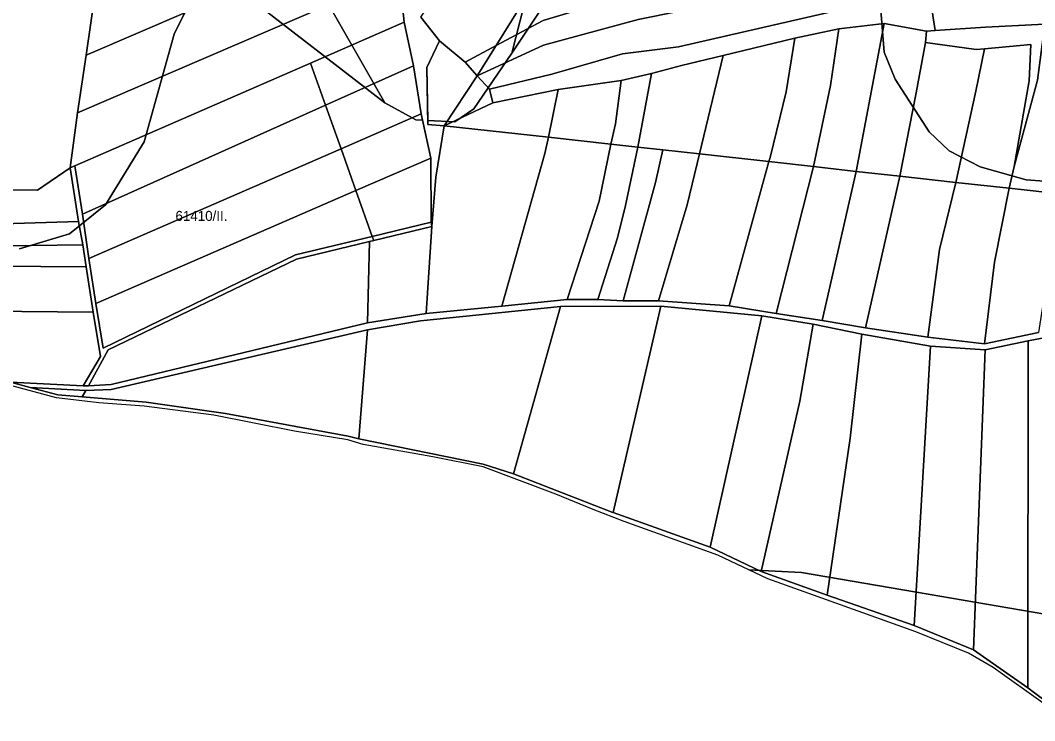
# Model space of a CAD drawing. Extents: x -521261 to -517465, y -1182764 to -1179456.
# Drawn here: x -520761 to -520253, y -1181838 to -1181488 of the extents above; entities that cross this region are included whole.
import ezdxf

# ---------------------------------------------------------------- set-up
doc = ezdxf.new("R2010")
doc.units = 0
for name, color, linetype in [('95560013', 7, 'Continuous'), ('95610013', 7, 'Continuous'), ('95620013', 7, 'Continuous'), ('95640013', 7, 'Continuous'), ('95660013', 7, 'Continuous')]:
    doc.layers.add(name, color=color, linetype=linetype)

msp = doc.modelspace()

# ---------------------------------------------------------------- linework, layer by layer
at = {"layer": '95560013'}
for points in [[(-520576.08, -1181410.39), (-520574.24, -1181438.77), (-520728.04, -1181505.07), (-520723.52, -1181473.69)], [(-520574.24, -1181438.77), (-520571.45, -1181464.53), (-520732.41, -1181533.87), (-520728.04, -1181505.07)], [(-520571.45, -1181464.53), (-520568.81, -1181488.5), (-520615.8, -1181509), (-520733.75, -1181560.43), (-520736.16, -1181561.46), (-520732.41, -1181533.87)], [(-520615.8, -1181509), (-520608.28, -1181530.11), (-520729.99, -1181584.7), (-520733.75, -1181560.43)], [(-520608.28, -1181530.11), (-520600.48, -1181552.02), (-520726.79, -1181606.86), (-520729.99, -1181584.7)], [(-520548.78, -1181540.39), (-520496.59, -1181546.1), (-520498.54, -1181554.32), (-520520.06, -1181630.73), (-520557.91, -1181634.34), (-520554.96, -1181590.89), (-520552.96, -1181566.19)], [(-520496.59, -1181546.1), (-520465.4, -1181549.66), (-520471.23, -1181578.21), (-520487.32, -1181627.42), (-520520.06, -1181630.73), (-520498.54, -1181554.32)], [(-520600.48, -1181552.02), (-520593.06, -1181572.76), (-520723.2, -1181629.37), (-520726.79, -1181606.86)], [(-520465.4, -1181549.66), (-520451.84, -1181551.12), (-520458.04, -1181580.38), (-520462.09, -1181596.51), (-520471.99, -1181627.44), (-520487.32, -1181627.42), (-520471.23, -1181578.21)], [(-520451.84, -1181551.12), (-520439.46, -1181552.51), (-520443.1, -1181568.75), (-520459.22, -1181628.09), (-520471.99, -1181627.44), (-520462.09, -1181596.51), (-520458.04, -1181580.38)], [(-520439.46, -1181552.51), (-520421.04, -1181554.54), (-520427.16, -1181580), (-520441.6, -1181628.06), (-520459.22, -1181628.09), (-520443.1, -1181568.75)], [(-520421.04, -1181554.54), (-520386.32, -1181558.37), (-520406.18, -1181630.57), (-520441.6, -1181628.06), (-520427.16, -1181580)], [(-520386.32, -1181558.37), (-520363.9, -1181560.85), (-520382.71, -1181634.48), (-520406.18, -1181630.57)], [(-520886.32, -1181568.63), (-520832.67, -1181568.56), (-520804.67, -1181572.45), (-520752.43, -1181572.59), (-520736.16, -1181561.46), (-520731.92, -1181588.39), (-520937.51, -1181594.75), (-520938.5, -1181584.87), (-520905.87, -1181574.73)], [(-520736.16, -1181561.46), (-520733.75, -1181560.43), (-520729.99, -1181584.7), (-520726.79, -1181606.86), (-520723.2, -1181629.37), (-520719.64, -1181651.68), (-520623.26, -1181604.99), (-520584.89, -1181595.78), (-520584.13, -1181597.91), (-520586.26, -1181598.42), (-520622.78, -1181607.14), (-520717.05, -1181652.63), (-520726.99, -1181670.56), (-520729.64, -1181670.6), (-520720.88, -1181655.89), (-520724.61, -1181633.78), (-520728.15, -1181611.04), (-520729.78, -1181600.02), (-520731.92, -1181588.39)], [(-520363.9, -1181560.85), (-520342.59, -1181563.26), (-520359.55, -1181637.84), (-520382.71, -1181634.48)], [(-520342.59, -1181563.26), (-520320.65, -1181565.69), (-520337.87, -1181641.62), (-520359.55, -1181637.84)], [(-520320.65, -1181565.69), (-520292.74, -1181568.76), (-520300.88, -1181602.38), (-520306.66, -1181646.26), (-520337.87, -1181641.62)], [(-520292.74, -1181568.76), (-520266.02, -1181571.63), (-520273.4, -1181608.7), (-520278.33, -1181649.59), (-520306.66, -1181646.26), (-520300.88, -1181602.38)], [(-520593.06, -1181572.76), (-520584.89, -1181595.78), (-520623.26, -1181604.99), (-520719.64, -1181651.68), (-520723.2, -1181629.37)], [(-520266.02, -1181571.63), (-520237.7, -1181574.77), (-520245.8, -1181608.4), (-520251.25, -1181643.84), (-520278.33, -1181649.59), (-520273.4, -1181608.7)], [(-520937.51, -1181594.75), (-520731.92, -1181588.39), (-520729.78, -1181600.02), (-520936.72, -1181602.63)], [(-520584.13, -1181597.91), (-520554.96, -1181590.89), (-520557.91, -1181634.34), (-520587.19, -1181639.08), (-520586.26, -1181598.42)], [(-520622.78, -1181607.14), (-520586.26, -1181598.42), (-520587.19, -1181639.08), (-520715.64, -1181669.99), (-520726.99, -1181670.56), (-520717.05, -1181652.63)], [(-520936.72, -1181602.63), (-520729.78, -1181600.02), (-520728.15, -1181611.04), (-520931.87, -1181609.45), (-520936.19, -1181607.92)], [(-520931.87, -1181609.45), (-520728.15, -1181611.04), (-520724.61, -1181633.78), (-520867.79, -1181632.34)], [(-520867.79, -1181632.34), (-520724.61, -1181633.78), (-520720.88, -1181655.89), (-520729.64, -1181670.6), (-520766.06, -1181668.83), (-520786.46, -1181661.6), (-520801.3, -1181657.2), (-520847.78, -1181646.82), (-520860.23, -1181635.71), (-520861.47, -1181634.59)], [(-520560.75, -1181638.05), (-520490.54, -1181630.82), (-520514.2, -1181714.71), (-520529.3, -1181709.77), (-520591.66, -1181697.2), (-520587.21, -1181642.65)], [(-520490.54, -1181630.82), (-520440.41, -1181630.77), (-520464.25, -1181734.09), (-520464.47, -1181734.01), (-520514.2, -1181714.71)], [(-520440.41, -1181630.77), (-520389.82, -1181635.53), (-520415.77, -1181751.31), (-520464.25, -1181734.09)], [(-520389.82, -1181635.53), (-520364.08, -1181639.81), (-520370.75, -1181678.21), (-520390.13, -1181763.62), (-520415.77, -1181751.31)], [(-520364.08, -1181639.81), (-520339.69, -1181644.68), (-520345.66, -1181696.87), (-520357.16, -1181775.41), (-520390.13, -1181763.62), (-520370.75, -1181678.21)], [(-520715.51, -1181672.43), (-520587.21, -1181642.65), (-520591.66, -1181697.2), (-520597, -1181695.88), (-520658.38, -1181684.44), (-520698.04, -1181678.72), (-520730.06, -1181676.1), (-520728.23, -1181673.03)], [(-520339.69, -1181644.68), (-520305.4, -1181650.72), (-520313.52, -1181790.53), (-520357.16, -1181775.41), (-520345.66, -1181696.87)], [(-520256.52, -1181648.14), (-520237.89, -1181644.57), (-520230.95, -1181838.28), (-520247.99, -1181828.33), (-520256.67, -1181821.86)], [(-520277.95, -1181652.57), (-520256.52, -1181648.14), (-520256.67, -1181821.86), (-520272.09, -1181811.02), (-520283.89, -1181802.78)], [(-520305.4, -1181650.72), (-520277.95, -1181652.57), (-520283.89, -1181802.78), (-520313.52, -1181790.53)], [(-520756.08, -1181671.43), (-520728.23, -1181673.03), (-520730.06, -1181676.1), (-520742.28, -1181675.11)]]:
    msp.add_lwpolyline(points, close=True, dxfattribs=at)
msp.add_lwpolyline([(-520237.89, -1181644.57), (-520256.52, -1181648.14), (-520277.95, -1181652.57), (-520305.4, -1181650.72), (-520339.69, -1181644.68), (-520364.08, -1181639.81), (-520389.82, -1181635.53), (-520440.41, -1181630.77), (-520490.54, -1181630.82), (-520560.75, -1181638.05), (-520587.21, -1181642.65), (-520715.51, -1181672.43), (-520728.23, -1181673.03), (-520756.08, -1181671.43), (-520766.06, -1181668.83), (-520729.64, -1181670.6), (-520726.99, -1181670.56), (-520715.64, -1181669.99), (-520587.19, -1181639.08), (-520557.91, -1181634.34), (-520520.06, -1181630.73), (-520487.32, -1181627.42), (-520471.99, -1181627.44), (-520459.22, -1181628.09), (-520441.6, -1181628.06), (-520406.18, -1181630.57), (-520382.71, -1181634.48), (-520359.55, -1181637.84), (-520337.87, -1181641.62), (-520306.66, -1181646.26), (-520278.33, -1181649.59), (-520251.25, -1181643.84)], dxfattribs=at)
at = {"layer": '95610013'}
for points in [[(-520454.87, -1181427.08), (-520391.32, -1181413.46), (-520408.16, -1181427.45), (-520448.41, -1181473.09), (-520453.82, -1181473.89), (-520499.28, -1181487.67), (-520522.86, -1181500.26), (-520482.21, -1181434.76)], [(-520364.32, -1181456), (-520313.09, -1181448.84), (-520310.06, -1181461.77), (-520349.03, -1181466.33), (-520451.71, -1181487.19), (-520499.12, -1181500), (-520532.26, -1181515.4), (-520522.86, -1181500.26), (-520499.28, -1181487.67), (-520453.82, -1181473.89), (-520448.41, -1181473.09), (-520445.12, -1181472.67)], [(-520310.06, -1181461.77), (-520307.52, -1181472.34), (-520307.98, -1181477.97), (-520351.52, -1181482.6), (-520431.47, -1181500.94), (-520459.61, -1181504.33), (-520494.99, -1181514.51), (-520526.22, -1181522.02), (-520532.26, -1181515.4), (-520499.12, -1181500), (-520451.71, -1181487.19), (-520349.03, -1181466.33)], [(-520305.37, -1181477.77), (-520303.01, -1181492.71), (-520307.36, -1181492.97), (-520328.5, -1181489.14), (-520351.25, -1181491.92), (-520373.3, -1181496.48), (-520409.22, -1181505.26), (-520429.99, -1181510.25), (-520445.11, -1181514.18), (-520460.28, -1181517.71), (-520491.73, -1181522.23), (-520524.43, -1181529), (-520526.22, -1181522.02), (-520494.99, -1181514.51), (-520459.61, -1181504.33), (-520431.47, -1181500.94), (-520351.52, -1181482.6), (-520307.98, -1181477.97)], [(-520373.3, -1181496.48), (-520351.25, -1181491.92), (-520355.45, -1181520.3), (-520363.9, -1181560.85), (-520386.32, -1181558.37), (-520385.73, -1181556.24), (-520377.61, -1181523.41)], [(-520351.25, -1181491.92), (-520328.5, -1181489.14), (-520342.59, -1181563.26), (-520363.9, -1181560.85), (-520355.45, -1181520.3)], [(-520328.5, -1181489.14), (-520307.36, -1181492.97), (-520307.94, -1181498.71), (-520312.51, -1181523.85), (-520320.65, -1181565.69), (-520342.59, -1181563.26)], [(-520248.06, -1181489.62), (-520251.84, -1181517.59), (-520263.43, -1181560.87), (-520255.94, -1181517.97), (-520255.16, -1181499.72), (-520278.35, -1181501.97), (-520282.48, -1181502.26), (-520307.94, -1181498.71), (-520307.36, -1181492.97), (-520303.01, -1181492.71), (-520277.86, -1181490.96)], [(-520222.29, -1181489.55), (-520229.64, -1181542.18), (-520237.7, -1181574.77), (-520266.02, -1181571.63), (-520263.43, -1181560.87), (-520251.84, -1181517.59), (-520248.06, -1181489.62)], [(-520409.22, -1181505.26), (-520373.3, -1181496.48), (-520377.61, -1181523.41), (-520385.73, -1181556.24), (-520386.32, -1181558.37), (-520421.04, -1181554.54)], [(-520282.48, -1181502.26), (-520278.35, -1181501.97), (-520282.61, -1181523.15), (-520292.74, -1181568.76), (-520320.65, -1181565.69), (-520312.51, -1181523.85), (-520307.94, -1181498.71)], [(-520278.35, -1181501.97), (-520255.16, -1181499.72), (-520255.94, -1181517.97), (-520263.43, -1181560.87), (-520266.02, -1181571.63), (-520292.74, -1181568.76), (-520282.61, -1181523.15)], [(-520429.99, -1181510.25), (-520409.22, -1181505.26), (-520421.04, -1181554.54), (-520439.46, -1181552.51), (-520451.84, -1181551.12), (-520445.11, -1181514.18)], [(-520532.26, -1181515.4), (-520526.22, -1181522.02), (-520524.43, -1181529), (-520548.78, -1181540.39)], [(-520491.73, -1181522.23), (-520460.28, -1181517.71), (-520463.12, -1181539.42), (-520465.4, -1181549.66), (-520496.59, -1181546.1)], [(-520460.28, -1181517.71), (-520445.11, -1181514.18), (-520451.84, -1181551.12), (-520465.4, -1181549.66), (-520463.12, -1181539.42)], [(-520524.43, -1181529), (-520491.73, -1181522.23), (-520496.59, -1181546.1), (-520548.78, -1181540.39)]]:
    msp.add_lwpolyline(points, close=True, dxfattribs=at)
at = {"layer": '95620013'}
msp.add_lwpolyline([(-520220.56, -1181464.03), (-520188.68, -1181456.43), (-520183.26, -1181487.11), (-520201.97, -1181488.21), (-520211.67, -1181488.9), (-520222.29, -1181489.55), (-520248.06, -1181489.62), (-520277.86, -1181490.96), (-520303.01, -1181492.71), (-520305.37, -1181477.77), (-520276.65, -1181475.26), (-520249.84, -1181470.67)], close=True, dxfattribs=at)
for points in [[(-520560.55, -1181486.11), (-520551.17, -1181497.81), (-520557.58, -1181511.29), (-520557.03, -1181539.8), (-520548.78, -1181540.39), (-520552.96, -1181566.19), (-520554.96, -1181590.89), (-520555.33, -1181588.67), (-520555.55, -1181556.57), (-520560.33, -1181534.47), (-520564.22, -1181510.35), (-520568.81, -1181488.5), (-520571.45, -1181464.53)], [(-520723.52, -1181473.69), (-520728.04, -1181505.07), (-520732.41, -1181533.87), (-520736.16, -1181561.46), (-520752.43, -1181572.59), (-520804.67, -1181572.45)]]:
    msp.add_lwpolyline(points, dxfattribs=at)
at = {"layer": '95640013'}
for points in [[(-520497.08, -1181439.12), (-520482.21, -1181434.76), (-520522.86, -1181500.26), (-520538.34, -1181508.53), (-520551.17, -1181497.81), (-520560.55, -1181486.11), (-520545.05, -1181462.49), (-520518.89, -1181450.27)], [(-520568.81, -1181488.5), (-520564.22, -1181510.35), (-520608.28, -1181530.11), (-520615.8, -1181509)], [(-520551.17, -1181497.81), (-520538.34, -1181508.53), (-520532.26, -1181515.4), (-520548.78, -1181540.39), (-520557.03, -1181539.8), (-520557.58, -1181511.29)], [(-520538.34, -1181508.53), (-520522.86, -1181500.26), (-520532.26, -1181515.4)], [(-520608.28, -1181530.11), (-520564.22, -1181510.35), (-520560.33, -1181534.47), (-520600.48, -1181552.02)], [(-520600.48, -1181552.02), (-520560.33, -1181534.47), (-520555.55, -1181556.57), (-520593.06, -1181572.76)], [(-520593.06, -1181572.76), (-520555.55, -1181556.57), (-520555.33, -1181588.67), (-520584.89, -1181595.78)], [(-520554.96, -1181590.89), (-520584.13, -1181597.91), (-520584.89, -1181595.78), (-520555.33, -1181588.67)]]:
    msp.add_lwpolyline(points, close=True, dxfattribs=at)
for points in [[(-520247.74, -1181830.3), (-520273.94, -1181811.64), (-520286.37, -1181804.39), (-520312.77, -1181793.79), (-520352.8, -1181779.41), (-520386.86, -1181767.21), (-520411.78, -1181755.41), (-520458.77, -1181738.57), (-520474.31, -1181732.61), (-520492.99, -1181724.81), (-520529.33, -1181711.19), (-520554.52, -1181706.12), (-520589.48, -1181699.97), (-520597.15, -1181697.6), (-520623.84, -1181693.35), (-520664.1, -1181685.3), (-520698.99, -1181680.78), (-520721.77, -1181679.06), (-520742.99, -1181676.7), (-520767.86, -1181669.98)], [(-520766.06, -1181668.83), (-520756.08, -1181671.43), (-520742.28, -1181675.11), (-520730.06, -1181676.1), (-520698.04, -1181678.72), (-520658.38, -1181684.44), (-520597, -1181695.88), (-520591.66, -1181697.2), (-520529.3, -1181709.77), (-520514.2, -1181714.71), (-520464.47, -1181734.01), (-520464.25, -1181734.09), (-520415.77, -1181751.31), (-520390.13, -1181763.62), (-520357.16, -1181775.41), (-520313.52, -1181790.53), (-520283.89, -1181802.78), (-520272.09, -1181811.02), (-520256.67, -1181821.86), (-520247.99, -1181828.33)]]:
    msp.add_lwpolyline(points, dxfattribs=at)
at = {"layer": '95660013'}
for points in [[(-520333.5, -1181440.5), (-520328.5, -1181503.5), (-520323, -1181517), (-520306, -1181543.5), (-520296, -1181553), (-520280.5, -1181561), (-520257.5, -1181567.5), (-520230, -1181569.5)], [(-520305.37, -1181477.77), (-520303.01, -1181492.71), (-520277.86, -1181490.96), (-520248.06, -1181489.62), (-520222.29, -1181489.55), (-520211.67, -1181488.9), (-520201.97, -1181488.21), (-520198.13, -1181505.28), (-520198.96, -1181527.88), (-520204.49, -1181561.93), (-520204.95, -1181563.97), (-520205, -1181564), (-520230, -1181569.5), (-520257.5, -1181567.5), (-520280.5, -1181561), (-520296, -1181553), (-520306, -1181543.5), (-520323, -1181517), (-520328.5, -1181503.5), (-520333.5, -1181440.5)], [(-520571.45, -1181464.53), (-520568.81, -1181488.5), (-520564.22, -1181510.35), (-520560.33, -1181534.47), (-520559.64, -1181537.67), (-520563, -1181537.5), (-520578.5, -1181529), (-520612.5, -1181469.5)], [(-520560.55, -1181486.11), (-520551.17, -1181497.81), (-520557.58, -1181511.29), (-520557.07, -1181537.8), (-520557.03, -1181539.8), (-520548.78, -1181540.39), (-520552.96, -1181566.19), (-520554.96, -1181590.89), (-520555.33, -1181588.67), (-520555.55, -1181556.57), (-520559.64, -1181537.67), (-520560.33, -1181534.47), (-520564.22, -1181510.35), (-520568.81, -1181488.5), (-520571.45, -1181464.53)], [(-520612.5, -1181469.5), (-520578.5, -1181529), (-520649.5, -1181474)], [(-520507, -1181472.5), (-520515, -1181504), (-520534, -1181532), (-520543.5, -1181538.5), (-520557.07, -1181537.8), (-520557.58, -1181511.29), (-520551.17, -1181497.81), (-520560.55, -1181486.11)], [(-520500, -1181481.5), (-520515, -1181504), (-520507, -1181472.5)], [(-520723.52, -1181473.69), (-520728.04, -1181505.07), (-520732.41, -1181533.87), (-520736.16, -1181561.46), (-520752.43, -1181572.59), (-520804.67, -1181572.45)], [(-520804.67, -1181572.45), (-520752.43, -1181572.59), (-520736.16, -1181561.46), (-520732.41, -1181533.87), (-520728.04, -1181505.07), (-520723.52, -1181473.69)], [(-520761.5, -1181602), (-520736.5, -1181594.5), (-520718.5, -1181580), (-520699, -1181548.5), (-520684, -1181494.5), (-520673.5, -1181473)], [(-520673.5, -1181473), (-520684, -1181494.5), (-520699, -1181548.5), (-520718.5, -1181580), (-520736.5, -1181594.5), (-520761.5, -1181602)], [(-520649.5, -1181474), (-520578.5, -1181529), (-520563, -1181537.5), (-520559.64, -1181537.67), (-520555.55, -1181556.57), (-520555.33, -1181588.67), (-520554.96, -1181590.89), (-520552.96, -1181566.19), (-520548.78, -1181540.39), (-520557.03, -1181539.8), (-520557.07, -1181537.8), (-520543.5, -1181538.5), (-520534, -1181532), (-520515, -1181504), (-520500, -1181481.5)], [(-520072.1, -1181478.37), (-520056.39, -1181494.56), (-520079.5, -1181516.84), (-520096.12, -1181530.34), (-520122.34, -1181546.18), (-520132.11, -1181550.97), (-520150.55, -1181560.01), (-520174.55, -1181568.61), (-520208.16, -1181578.29), (-520204.95, -1181563.97), (-520204.49, -1181561.93), (-520198.96, -1181527.88), (-520198.13, -1181505.28), (-520201.97, -1181488.21), (-520211.67, -1181488.9), (-520222.29, -1181489.55), (-520248.06, -1181489.62), (-520277.86, -1181490.96), (-520303.01, -1181492.71), (-520305.37, -1181477.77)], [(-520219, -1181790), (-520306.5, -1181775), (-520370, -1181764), (-520396.38, -1181762.7), (-520411.78, -1181755.41), (-520458.77, -1181738.57), (-520474.31, -1181732.61), (-520492.99, -1181724.81), (-520529.33, -1181711.19), (-520554.52, -1181706.12), (-520589.48, -1181699.97), (-520597.15, -1181697.6), (-520623.84, -1181693.35), (-520664.1, -1181685.3), (-520698.99, -1181680.78), (-520721.77, -1181679.06), (-520742.99, -1181676.7), (-520767.86, -1181669.98)], [(-520247.74, -1181830.3), (-520273.94, -1181811.64), (-520286.37, -1181804.39), (-520312.77, -1181793.79), (-520352.8, -1181779.41), (-520386.86, -1181767.21), (-520396.38, -1181762.7), (-520370, -1181764), (-520306.5, -1181775), (-520219, -1181790)]]:
    msp.add_lwpolyline(points, dxfattribs=at)

# ---------------------------------------------------------------- texts
msp.add_text('61410/II.', height=5, rotation=0, dxfattribs=at).set_placement((-520683.39, -1181588.03))

doc.saveas('drawing.dxf')
